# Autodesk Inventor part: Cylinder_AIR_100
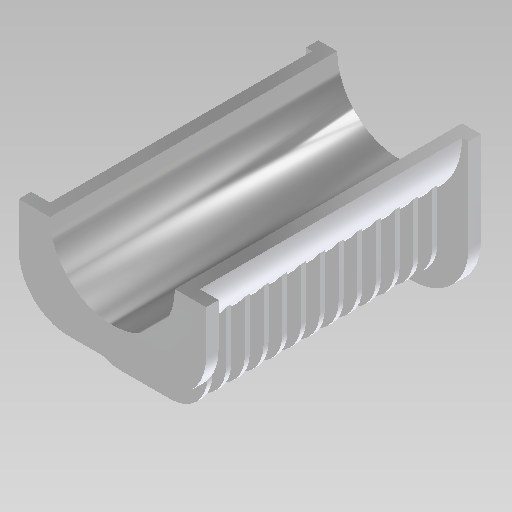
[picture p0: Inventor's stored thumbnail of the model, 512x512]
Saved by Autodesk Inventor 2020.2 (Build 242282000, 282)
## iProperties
Created: 2014-10
Part Number: Cylinder_AIR_100
Material: Aluminium 6061
Document SubType Name: Modeling
Designer: F.Stasiak
Density: 2.7 g/cm^3
Appearance: Aluminium - płaski
Catalog Web Link: www.expertbooks.pl
Manager: www.cadconsulting.pl
Company: Fabian Stasiak CAD Consulting
Author: F.Stasiak
Subject: Zbiór ćwiczeń. Autodesk Inventor 2020. Kurs Professional
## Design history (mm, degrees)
sketch "Szkic1"
  geometry: L1 (37.033, 74.098)-(37.033, -74.098) reference; L2 (20.098, -91.033)-(-20.098, -91.033) reference; L3 (-37.033, -74.098)-(-37.033, 74.098) reference; L4 (-20.098, 91.033)-(20.098, 91.033) reference; L5 (-65.064, 74.159)-(-65.064, -74.159) reference; L6 (-20.159, -119.064)-(20.159, -119.064) reference; L7 (65.064, -74.159)-(65.064, 74.159) reference; L8 (20.159, 119.064)-(-20.159, 119.064) reference; C1 r 50 at (0, 0); C2 r 60 at (0, 0); 5 further points; 4 other entities
  constraints: 2 centre point, 2 coincident, 4 other
  dimensions: "d2" = 100 diameter of C1; "d3" = 120 diameter of C2
extrude "Wyciągnięcie proste2" new body sketch "Szkic1" distance "d4" = 220; taper "d5" = 0 deg
sketch "Szkic2"
  geometry: L1 (-65.064, -74.159)-(-65.064, 74.159) reference; L2 (20.159, -119.064)-(-20.159, -119.064) reference; L3 (65.064, 74.159)-(65.064, -74.159) reference; L4 (-20.159, 119.064)-(20.159, 119.064) reference; C1 r 50 at (0, 0) reference; 2 further points
extrude "Wyciągnięcie proste3" join sketch "Szkic2" distance "d6" = 10; taper "d7" = 0 deg
node "Płaszczyzna konstrukcyjna1"
sketch "Szkic3"
  geometry: L1 (65.064, -74.159)-(65.064, 74.159) reference; L2 (20.159, 119.064)-(-20.159, 119.064) reference; L3 (-65.064, 74.159)-(-65.064, -74.159) reference; L4 (-20.159, -119.064)-(20.159, -119.064) reference; L5 (20.159, -104.064)-(-20.159, -104.064); L6 (-20.159, 104.064)-(20.159, 104.064); L7 (50.064, 74.159)-(50.064, 33.07); L8 (50.064, -33.07)-(50.064, -74.159); L9 (-50.064, -74.159)-(-50.064, -33.07); L10 (-50.064, 33.07)-(-50.064, 74.159); C1 r 60 at (0, 0) reference; A1 r 60 centre (0, 0) between (50.064, 33.07) and (50.064, -33.07) reference; 1 further point
  constraints: 12 end point, 4 parallel, 4 point on circle, 16 other
extrude "Wyciągnięcie proste4" join sketch "Szkic3" distance "d10" = 4; taper "d11" = 0 deg
pattern_linear "Szyk prostokątny1" dims "d14" = 15
sketch "Szkic4"
  geometry: L1 (75, 75)-(-75, 75); L2 (-75, 75)-(-75, -75); L3 (-75, -75)-(75, -75); L4 (75, -75)-(75, 75); L5 (75, 75)-(-75, -75); L6 (-75, 75)-(75, -75); C1 r 50 at (0, 0) reference; C2 r 60 at (0, 0) reference; 1 further point
  constraints: 12 end point, 2 midpoint, 2 parallel, 1 horizontal, 1 perpendicular
  dimensions: "d15" = 150 distance of L3.end L2.end; "d16" = 150 distance of L2.end L1.end
extrude "Wyciągnięcie proste5" join sketch "Szkic4" distance "d17" = 10; taper "d18" = 0 deg
fillet "Zaokrąglenie1" dims "d19" = 40
feature "Podział1"
node "Bryła2"
node "Odniesienie1"
node "Odniesienie2"
node "Pętla rzutowana1"
node "Pętla rzutowana2"
other parameters: "d9" = 15
